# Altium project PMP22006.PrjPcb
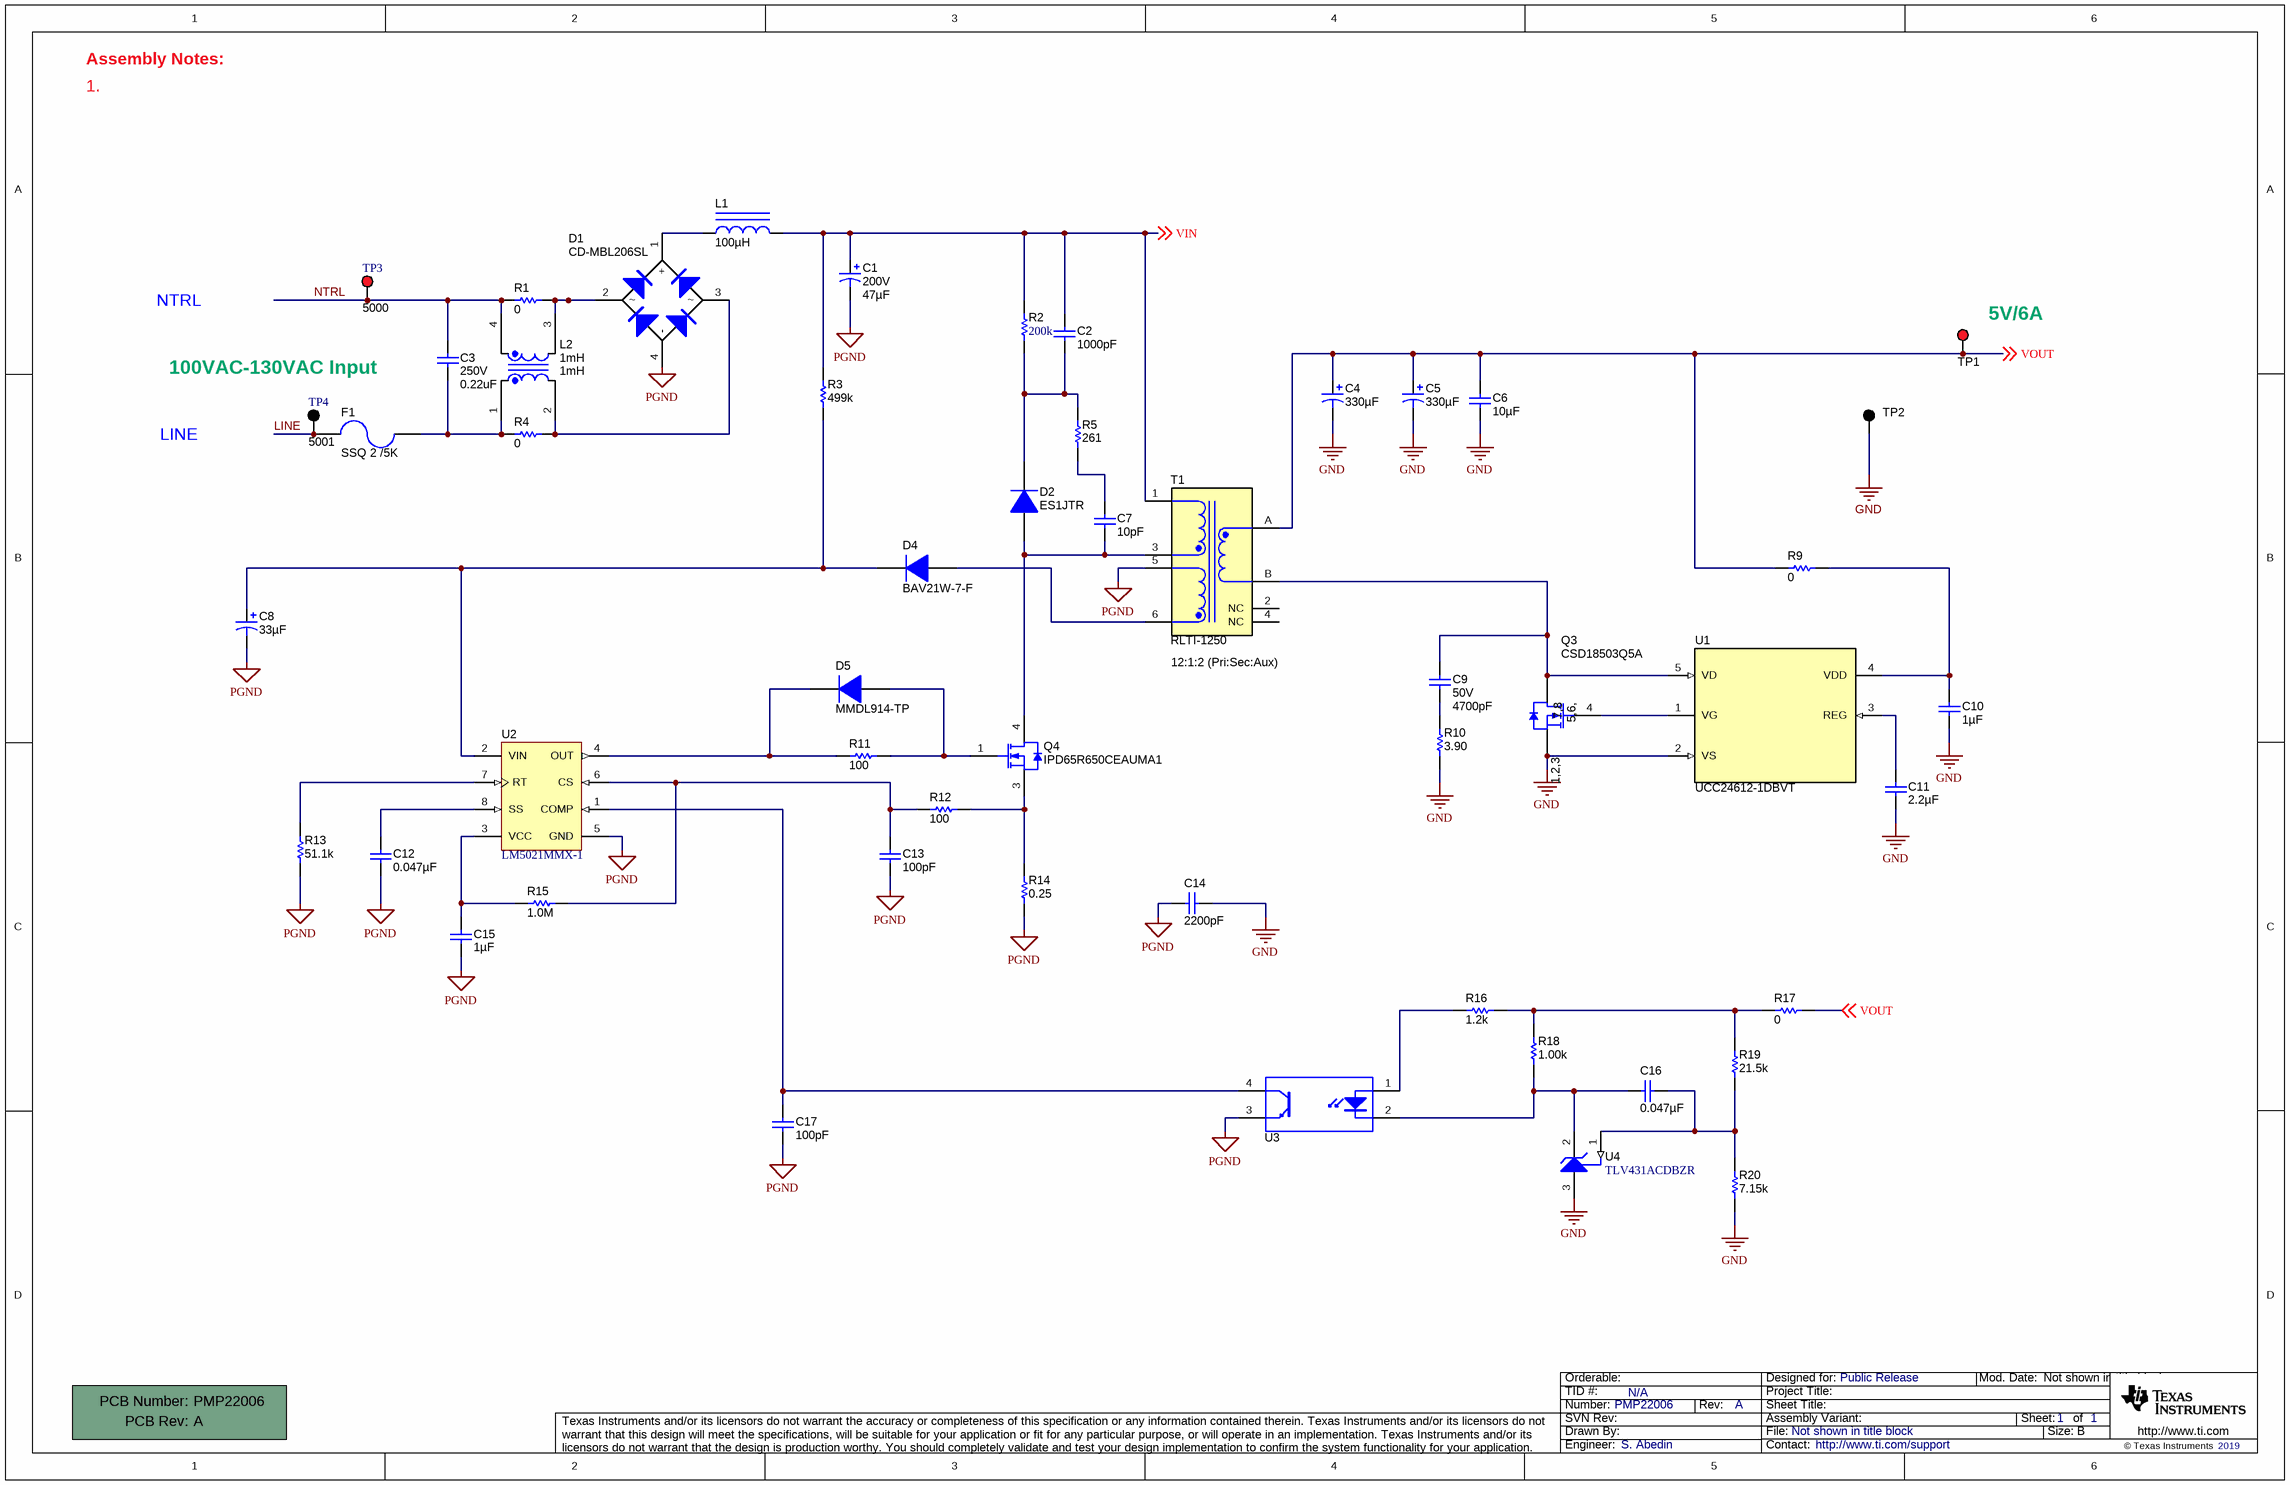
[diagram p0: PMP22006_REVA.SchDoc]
CopyrightYear: 2019; PCB_Layout: S. Abedin; PCB_Rev: A; PRJ_Customer: Public Release; PRJ_Engineer: S. Abedin; PRJ_Number: PMP22006; SCH_Rev: A; TechSupport: http://www.ti.com/support; TID: N/A
1 sheet, 53 parts. Net scope: global (net labels, ports and power ports of the same name join across sheets).
Board file: PMP22006_PCB.PcbDoc

## Sheet PMP22006_REVA.SchDoc
size 431 x 279 mm; Date: Not shown in title block; ApprovedBy: Not shown in title block; CheckedBy: Not shown in title block; Author: Not shown in title block; CompanyName: Not shown in title block; Engineer: Not shown in title block; Organization: Not shown in title block; Address1: Not shown in title block; Address2: Not shown in title block; Address3: Not shown in title block; Address4: Not shown in title block; DocumentNumber: 1; Revision: Use project parameter SCH_Rev; SheetNumber: 1; SheetTotal: 1; PageSetup: Record=PageOptions¦CenterHorizontal=True¦CenterVertical=True¦PrintScale=1.00¦XCorrection=1.00¦YCorrection=1.00¦PrintKind=0¦BorderSize=5000000¦LeftOffset=0¦BottomOffset=0¦Orientation=2¦PaperLength=1000¦PaperWidth=1000¦Scale=100¦PaperSource=15¦PrintQuality=600¦MediaType=1¦DitherType=10¦PaperKind=Letter¦PrintScaleMode=1

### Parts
!PCB1  Printed Circuit Board  (value not drawn)  (mechanical)
C1  VDC_V: 200V  ValueDisplayed: 47µF  [Nichicon_1250x2000_HorizontalUP]  (hidden comment: UCS2D470MHD)
C2  ValueDisplayed: 1000pF  [1206L]  (hidden comment: GRM31A7U2J102JW31D)
C3  VDC_V: 250V  ValueDisplayed: 0.22uF  [CAPRR500W60L780T780H1300]  (hidden comment: B32529D3224J)
C4  ValueDisplayed: 330µF  [S8_630x800]  (hidden comment: RS80J331MDNASQJT)
C5  ValueDisplayed: 330µF  [S8_630x800]  (hidden comment: RS80J331MDNASQJT)
C6  ValueDisplayed: 10µF  [0603]  (hidden comment: C1608X6S1A106M080AC)
C7  ValueDisplayed: 10pF  [1206L]  (hidden comment: VJ1206A100JXGAT5Z)
C8  ValueDisplayed: 33µF  [Rubycon_500x1100]  (hidden comment: 35YXH33MEFC5X11)
C9  VDC_V: 50V  ValueDisplayed: 4700pF  [0402]  (hidden comment: C1005X7R1H472K050BA)
C10  ValueDisplayed: 1µF  [0402L]  (hidden comment: GRM155R60J105KE19D)
C11  ValueDisplayed: 2.2µF  [0603L]  (hidden comment: GRM188R61C225KAAD)
C12  ValueDisplayed: 0.047µF  [0402L]  (hidden comment: GRM155R71E473KA88D)
C13  ValueDisplayed: 100pF  [0402L]  (hidden comment: GRM1555C1H101JA01D)
C14  ValueDisplayed: 2200pF  [CD45_900x600x1300]  (hidden comment: CD45-E2GA222M-NKA)
C15  ValueDisplayed: 1µF  [0603L]  (hidden comment: GRM188R61E105KA12D)
C16  ValueDisplayed: 0.047µF  [0402L]  (hidden comment: GRM155R71E473KA88D)
C17  ValueDisplayed: 100pF  [0402L]  (hidden comment: GRM1555C1H101JA01D)
D1  CD-MBL206SL  [CD-MBL2xxS]
D2  ES1JTR  [SMA]
D4  BAV21W-7-F  [SOD-123]
D5  MMDL914-TP  [SOD-323]
F1  SSQ 2 /5K  [6125FA]
L1  ValueDisplayed: 100µH  [SRN6045]  (hidden comment: SRN6045-101M)
L2  value 1mH  [WE-CMB_XS]  (hidden comment: 744821201)
Q3  CSD18503Q5A  [DQJ0008A]
Q4  IPD65R650CEAUMA1  [DPAK]
R1  ValueDisplayed: 0  [1206L]  (hidden comment: CRCW12060000Z0EA)
R2  ValueDisplayed: 200k  [1210L]  (hidden comment: ERJ-14NF2003U)
R3  ValueDisplayed: 499k  [1206L]  (hidden comment: CRCW1206499KFKEA)
R4  ValueDisplayed: 0  [1206L]  (hidden comment: CRCW12060000Z0EA)
R5  ValueDisplayed: 261  [2010]  (hidden comment: CRCW2010261RFKEF)
R9  ValueDisplayed: 0  [0402L]  (hidden comment: CRCW04020000Z0ED)
R10  ValueDisplayed: 3.90  [1206]  (hidden comment: ERJ-8RQF3R9V)
R11  ValueDisplayed: 100  [0402L]  (hidden comment: CRCW0402100RFKED)
R12  ValueDisplayed: 100  [0402L]  (hidden comment: CRCW0402100RFKED)
R13  ValueDisplayed: 51.1k  [0402]  (hidden comment: CRCW040251K1FKED)
R14  ValueDisplayed: 0.25  [1206L]  (hidden comment: CSR1206FKR250)
R15  ValueDisplayed: 1.0M  [0402L]  (hidden comment: CRCW04021M00JNED)
R16  ValueDisplayed: 1.2k  [0402]  (hidden comment: CRCW04021K20JNED)
R17  ValueDisplayed: 0  [0402L]  (hidden comment: CRCW04020000Z0ED)
R18  ValueDisplayed: 1.00k  [0603L]  (hidden comment: CRCW06031K00FKEA)
R19  ValueDisplayed: 21.5k  [0402L]  (hidden comment: CRCW040221K5FKED)
R20  ValueDisplayed: 7.15k  [0402]  (hidden comment: CRCW04027K15FKED)
T1  RLTI-1250  [Renco_RLTI-1250]
TP1  5000  [Keystone5000]  (value not drawn)
TP2  5001  [Keystone5001]  (value not drawn)
TP3  5000  [Keystone5000]
TP4  5001  [Keystone5001]
U1  UCC24612-1DBVT  [DBV0005A_L]
U2  LM5021MMX-1  [MUA08A_L]
U3  LTV-817A  [DIP254P762X350-4]  (value not drawn)
U4  TLV431ACDBZR  [DBZ0003A_N]

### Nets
GND: C4.2(-) C5.2(-) C6.2 C10.2 C11.2 C14.1 Q3.1(S) Q3.2(S) Q3.3(S) R10.1 R20.1 TP2.1 U1.2(VS) U4.3(ANODE)
PGND: C1.2(-) C8.2(-) C12.1 C13.1 C14.2 C15.2 C17.1 D1.4(-) R13.1 R14.2 T1.5 U2.5(GND) U3.3(E)
LINE: F1.2 TP4.1
NTRL: C3.1 L2.4 R1.1 TP3.1
VIN: C1.1(+) C2.1 L1.2 R2.2 R3.2 T1.1 ; off-sheet VIN
VOUT: C4.1(+) C5.1(+) C6.1 R9.1 R17.2 T1.A TP1.1 ; off-sheet VOUT
NetC2_2: C2.2 D2.1(K) R2.1 R5.2
NetC3_2: C3.2 F1.1 L2.1 R4.1
NetC7_1: C7.1 R5.1
NetC7_2: C7.2 D2.2(A) Q4.4(D) T1.3
NetC8_1: C8.1(+) D4.1(K) R3.1 U2.2(VIN)
NetC9_1: C9.1 Q3.5(D) Q3.6(D) Q3.7(D) Q3.8(D) Q3.9(D) T1.B U1.5(VD)
NetC9_2: C9.2 R10.2
NetC10_1: C10.1 R9.2 U1.4(VDD)
NetC11_1: C11.1 U1.3(REG)
NetC12_2: C12.2 U2.8(SS)
NetC13_2: C13.2 R12.2 R15.1 U2.6(CS)
NetC15_1: C15.1 R15.2 U2.3(VCC)
NetC16_1: C16.1 R18.2 U3.2(K) U4.2(CATHODE)
NetC16_2: C16.2 R19.1 R20.2 U4.1(REF)
NetC17_2: C17.2 U2.1(COMP) U3.4(C)
NetD1_1: D1.1(+) L1.1
NetD1_2: D1.2 L2.3 R1.2
NetD1_3: D1.3 L2.2 R4.2
NetD4_2: D4.2(A) T1.6
NetD5_1: D5.1(K) R11.2 U2.4(OUT)
NetD5_2: D5.2(A) Q4.1(G) R11.1
NetQ3_4: Q3.4(G) U1.1(VG)
NetQ4_3: Q4.3(S) R12.1 R14.1
NetR13_2: R13.2 U2.7(RT)
NetR16_1: R16.1 U3.1(A)
NetR16_2: R16.2 R17.1 R18.1 R19.2

Not connected (* = marked no-connect by the designer): T1 2(NC) 4(NC)

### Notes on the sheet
- Assembly Notes:
- 1.
- NTRL
- 100VAC-130VAC Input
- (near TP1) 5V/6A
- LINE
- (near T1) 12:1:2 (Pri:Sec:Aux)

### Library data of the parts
!PCB1 = PCB: Manufacturer: Any; PartNumber: PMP22006; SymbolCreator: a0412235
C1 = CMP-0076769-1: CAP, AL, 47 µF, 200 V, +/- 20%, TH; Manufacturer: Nichicon; IRMS_A: 9.8dA; SizeAreaWB_mm2: 210.25; SizeArea_mm2: 156.25; AEC Qualified: N; AEC Category: Q200; Value: 47uF; TaMax_C: 105°C; SizeZ_mm: 21.5; Polarized: Y; TaMin_C: -40°C; SizeY_mm: 12.5; U/M: EA; CompType: Capacitor; Cap_Case: 12.5x20mm
C2 = GRM31A7U2J102JW31D: CAP, CERM, 1000 pF, 630 V,+/- 5%, U2J, 1206; Manufacturer: MuRata; Polarized: N; CompType: Capacitor; Value: 1000pF; U/M: EA; Cap_F: 0.000000001; Tolerance_%: 5; VDC_V: 630; Value2: 630V; TaMin_C: -55; TaMax_C: 125; Cap_Case: 1206; SizeArea_mm2: 5.12; SizeAreaWB_mm2: 10.92; SizeX_mm: 3.2; SizeY_mm: 1.6; SizeZ_mm: 1.35; AEC Category: Q200
C3 = CMP-0012341-1: CAP, Film, 0.22 uF, 250 V, +/- 5%, TH; Manufacturer: TDK; TaMin_C: -55°C; Polarized: N; SizeAreaWB_mm2: 96.04; Value1: Unknown; U/M: EA; Value: 0.22uF; TaMax_C: 125°C; SizeZ_mm: 13; SizeX_mm: 7.8; Cap_Case: 7.8x13x7.8; SizeArea_mm2: 60.84; Cap_F: 220nF; AEC Category: Q200
C4 C5 = RS80J331MDNASQJT: CAP, Aluminum Polymer, 330 µF, 6.3 V,+/- 20%, 0.008 ohm, TH; Manufacturer: Nichicon; Polarized: Y; CompType: Capacitor; Value: 330uF; U/M: EA; Cap_F: 0.00033; Tolerance_%: 20; VDC_V: 6.3; Value2: 6.3V; ESR_ohm: 0.008; IRMS_A: 5; TaMin_C: -55; TaMax_C: 105; Cap_Case: 6.3X8mm; SizeAreaWB_mm2: 68.89; SizeArea_mm2: 39.69; SizeZ_mm: 9; AEC Category: Q200; AEC Qualified: N
C6 = C1608X6S1A106M080AC: CAP, CERM, 10 µF, 10 V,+/- 10%, X6S, 0603; Manufacturer: TDK; Polarized: N; CompType: Capacitor; Value: 10uF; U/M: EA; Cap_F: 0.00001; Tolerance_%: 10; ESR_ohm: 0.004639; Value1: 0.004639 ohm; Value2: 10V; IRMS_A: 2.41407; TaMin_C: -55; TaMax_C: 105; SizeArea_mm2: 1.28; SizeAreaWB_mm2: 4.68; SizeX_mm: 1.6; SizeY_mm: 0.8; SizeZ_mm: 1; AEC Category: Q200
C7 = VJ1206A100JXGAT5Z: CAP, CERM, 10 pF, 1000 V,+/- 5%, C0G/NP0, 1206; Manufacturer: Vishay-Vitramon; Polarized: N; CompType: Capacitor; Value: 10pF; U/M: EA; Cap_F: 0.00000000001; Tolerance_%: 5; VDC_V: 1000; Value2: 1000V; TaMin_C: -55; TaMax_C: 125; Cap_Case: 1206; SizeArea_mm2: 5.12; SizeAreaWB_mm2: 10.92; SizeX_mm: 3.2; SizeY_mm: 1.6; SizeZ_mm: 1.35; AEC Category: Q200
C8 = 35YXH33MEFC5X11: CAP, AL, 33 µF, 35 V, +/- 20%, TH; Manufacturer: Rubycon; Polarized: Y; CompType: Capacitor; Value: 33uF; U/M: EA; Cap_F: 0.000033; Tolerance_%: 20; Value1: Unknown; VDC_V: 35; Value2: 35V; IRMS_A: 0.21; TaMin_C: -40; TaMax_C: 105; Cap_Case: 5x11mm; SizeAreaWB_mm2: 49; SizeArea_mm2: 25; SizeX_mm: 5; SizeZ_mm: 12.5; AEC Category: Q200; AEC Qualified: N
C9 = CMP-0078221-1: CAP, CERM, 4700 pF, 50 V,+/- 10%, X7R, 0402; Manufacturer: TDK; TaMin_C: -55°C; Polarized: N; SizeAreaWB_mm2: 3; U/M: EA; Value: 4700pF; TaMax_C: 125°C; SizeZ_mm: 0.6; SizeX_mm: 1; SizeY_mm: 0.5; Cap_F: 4.7nF; AEC Category: Q200
C10 = GRM155R60J105KE19D: CAP, CERM, 1 µF, 6.3 V, +/- 10%, X5R, 0402; Manufacturer: MuRata; Polarized: N; CompType: Capacitor; Value: 1uF; U/M: EA; Cap_F: 0.000001; Tolerance_%: 10; Value1: Unknown; VDC_V: 6.3; Value2: 6.3V; TaMin_C: -55; TaMax_C: 85; Cap_Case: 0402; SizeArea_mm2: 0.5; SizeAreaWB_mm2: 3; SizeX_mm: 1; SizeZ_mm: 0.6; AEC Category: Q200
C11 = GRM188R61C225KAAD: CAP, CERM, 2.2 µF, 16 V,+/- 10%, X5R, 0603; Manufacturer: MuRata; Polarized: N; CompType: Capacitor; Value: 2.2uF; U/M: EA; Cap_F: 0.0000022; Tolerance_%: 10; Value1: Unknown; VDC_V: 16; Value2: 16V; TaMin_C: -55; TaMax_C: 85; Cap_Case: 0603; SizeArea_mm2: 1.28; SizeAreaWB_mm2: 4.68; SizeX_mm: 1.6; SizeY_mm: 0.8; SizeZ_mm: 1; AEC Category: Q200; Green_Lifecycle: Not Set; Green_REACh: Incomplete
C12 C16 = GRM155R71E473KA88D: CAP, CERM, 0.047 µF, 25 V, +/- 10%, X7R, 0402; Manufacturer: MuRata; Polarized: N; CompType: Capacitor; Value: 0.047uF; U/M: EA; Cap_F: 0.000000047; Tolerance_%: 10; Value1: Unknown; VDC_V: 25; Value2: 25V; TaMin_C: -55; TaMax_C: 125; Cap_Case: 0402; SizeArea_mm2: 0.5; SizeAreaWB_mm2: 3; SizeX_mm: 1; SizeZ_mm: 0.6; AEC Category: Q200
C13 C17 = GRM1555C1H101JA01D: CAP, CERM, 100 pF, 50 V,+/- 5%, C0G/NP0, 0402; Manufacturer: MuRata; Polarized: N; CompType: Capacitor; Value: 100pF; U/M: EA; Cap_F: 0.0000000001; Tolerance_%: 5; Value1: Unknown; VDC_V: 50; Value2: 50V; TaMin_C: -55; TaMax_C: 125; Cap_Case: 0402; SizeArea_mm2: 0.5; SizeAreaWB_mm2: 3; SizeX_mm: 1; SizeZ_mm: 0.6; AEC Category: Q200; Green_Lifecycle: Active; Green_REACh: Passed
C14 = CD45-E2GA222M-NKA: CAP, CERM, 2200 pF,  V, +/- 20%, E, D9xT6mm; Manufacturer: TDK; Value: 2200pF; Polarized: N; CompType: Capacitor; U/M: EA; Cap_F: 0.0000000022; Tolerance_%: 20; Value1: Unknown; TaMin_C: -25; TaMax_C: 125; Cap_Case: 9x6x13mm; SizeArea_mm2: 63.9; SizeAreaWB_mm2: 101.2; SizeX_mm: 10.65; SizeY_mm: 6; SizeZ_mm: 13; AEC Category: Q200
C15 = GRM188R61E105KA12D: CAP, CERM, 1 µF, 25 V, +/- 10%, X5R, 0603; Manufacturer: MuRata; Polarized: N; CompType: Capacitor; Value: 1uF; U/M: EA; Cap_F: 0.000001; Tolerance_%: 10; Value1: Unknown; VDC_V: 25; Value2: 25V; TaMin_C: -55; TaMax_C: 85; Cap_Case: 0603; SizeArea_mm2: 1.28; SizeAreaWB_mm2: 4.68; SizeX_mm: 1.6; SizeY_mm: 0.8; SizeZ_mm: 1; AEC Category: Q200
D1 = CD-MBL206SL: Diode, P-N-Bridge, 600 V, 2 A, 5.8x5.3mm; Manufacturer: Bourns; U/M: EA; Vf_V: 0.96; Value: 600V; Value1: 2A; Value2: 0.96V; Io_A: 2; Vr_V: 600; TJmax_C: 175; RJC_CperW: 15; SizeAreaWB_mm2: 47.092; SizeArea_mm2: 23.452; SizeX_mm: 5.72; SizeY_mm: 4.1; SizeZ_mm: 1.35; AEC Category: Q101; AEC Qualified: N
D2 = ES1JTR: Diode, Superfast Rectifier, 600 V, 1 A, SMA; Manufacturer: SMC Diode Solutions; U/M: EA; Vf_V: 1.7; Value: 600V; Value1: 1A; Value2: 1.7V; Io_A: 1; Vr_V: 600; TJmax_C: 150; RJC_CperW: 35; SizeAreaWB_mm2: 37.3428; SizeArea_mm2: 16.3228; SizeX_mm: 5.59; SizeY_mm: 2.92; SizeZ_mm: 2.87; AEC Category: Q101; AEC Qualified: N
D4 = BAV21W-7-F: Diode, Switching, 200 V, 0.2 A, SOD-123; Manufacturer: Diodes Inc.; U/M: EA; Vf_V: 1.25; Value: 200V; Value1: 0.2A; Value2: 1.25V; Io_A: 0.2; Vr_V: 200; TJmax_C: 150; SizeAreaWB_mm2: 13.095; SizeArea_mm2: 6.545; SizeX_mm: 3.85; SizeY_mm: 1.7; SizeZ_mm: 1.35; AEC Category: Q101; Green_Lifecycle: Active; Green_REACh: Passed
D5 = MMDL914-TP: Diode, Switching, 100 V, 0.2 A, SOD-323; Manufacturer: Micro Commercial Components; U/M: EA; Vf_V: 1; Value: 100V; Value1: 0.2A; Value2: 1V; Io_A: 0.2; Vr_V: 100; TJmax_C: 150; SizeAreaWB_mm2: 8.695; SizeArea_mm2: 3.645; SizeX_mm: 2.7; SizeY_mm: 1.35; AEC Category: Q101
F1 = 6125FA2A: Fuse, 2 A, 125VAC/VDC, SMD; Manufacturer: Bel Fuse Inc.; VDC_V: 125; Interrupt_DC: 300; Interrupt_AC: 50; Irating_A: 2; Rtyp_Ohm: 0.05; MeltingTyp: 0.8
L1 = SRN6045-680M: FIXED IND 100UH 700MA 494 MOHM; Manufacturer: Bourns; CompType: Inductor; Ind_H: 68.0E-6; Imax_A: 0.9; Irms: 0.9A @ 40C rise; Isat: 1A @ 30% inductance drop; DCR_ohm: 0.351; Value1: 0.351 ohm; Value2: 0.9A; Material: Ferrite; SizeAreaWB_mm2: 64; SizeArea_mm2: 36; SizeX_mm: 6; SizeZ_mm: 4.5; AEC Category: Q200
L2 = CMP-0013113-1: Coupled inductor, 1 mH, 2 A, 0.045 ohm, TH; Manufacturer: Wurth Elektronik; SizeAreaWB_mm2: 161.5; DCR_ohm: 0.045; SizeZ_mm: 20.5; SizeX_mm: 15; SizeY_mm: 7.5; SizeArea_mm2: 112.5
Q3 = CSD18503Q5A: MOSFET, N-CH, 40 V, 100 A, DQJ0008A (VSONP-8); Manufacturer: Texas Instruments; Alternate Manufacturer: None; U/M: EA; ChType: N; Value: 40V; VdsMax_V: 40; Value1: 0.0062 ohm; Rdson45_ohm: 0.0062; Value2: 13 nC; QgTyp_nC: 13; Vgs_V: 20; IdsMax_A: 100; SizeAreaWB_mm2: 55.2; SizeArea_mm2: 29.4; SizeX_mm: 6; SizeY_mm: 4.9; SizeZ_mm: 1.1; AEC Category: Q101
Q4 = IPD65R650CEAUMA1: MOSFET, N-CH, 650 V, 10.1 A, DPAK; Manufacturer: Infineon Technologies; Alternate Manufacturer: None; U/M: EA; ChType: N; Value: 650V; VdsMax_V: 650; Value1: ? ohm; Value2: 23 nC; QgTyp_nC: 23; Vgs_V: 20; IdsMax_A: 10.1; SizeAreaWB_mm2: 101.7114; SizeArea_mm2: 64.8114; SizeX_mm: 9.91; SizeY_mm: 6.54; SizeZ_mm: 2.29; AEC Category: Q101
R1 R4 = CRCW12060000Z0EA: RES, 0, 5%, 0.25 W, 1206; Manufacturer: Vishay-Dale; CompType: Resistor; Value: 0; Value_Code: 0000; Tolerance_%: 5; Power_W: 0.25; Value2: 0.25W; VDC_V: 200; TempCo: 200 ppm/C; EIA_Code: E24; U/M: EA; AEC Category: Q200
R2 = ERJ-14NF2003U: RES, 200 k, 1%, 0.5 W, 1210; Manufacturer: Panasonic; CompType: Resistor; Value: 200k; Res_ohm: 200000; Tolerance_%: 1; Power_W: 0.5; Value2: 0.5W; VDC_V: 200; TempCo: 100 ppm/C; SizeArea_mm2: 8; SizeAreaWB_mm2: 14.7; SizeX_mm: 3.2; SizeY_mm: 2.5; SizeZ_mm: 1.35; EIA_Code: E96; U/M: EA; AEC Category: Q200
R3 = CRCW1206499KFKEA: RES, 499 k, 1%, 0.25 W, 1206; Manufacturer: Vishay-Dale; CompType: Resistor; Value: 499k; Res_ohm: 499000; Tolerance_%: 1; Power_W: 0.25; Value2: 0.25W; VDC_V: 200; TempCo: 100 ppm/C; SizeArea_mm2: 5.12; SizeX_mm: 3.2; SizeY_mm: 1.6; SizeZ_mm: 1.35; EIA_Code: E96; U/M: EA; AEC Category: Q200; Green_Lifecycle: Active; Green_REACh: Passed
R5 = CMP-0016331-2: RES, 261, 1%, 0.75 W, AEC-Q200 Grade 0, 2010; Manufacturer: Vishay-Dale; Power_W: 750mW; TempCo: 100 ppm/C; Value_Code: 261R; U/M: EA; Value: 261; EIA_Code: E96; SizeX_mm: 5; SizeY_mm: 2.5; SizeZ_mm: 1.66; Value2: 0.75W; SizeArea_mm2: 12.5; AEC Qualified: Y; VDC_V: 400V; AEC Grade: 0; AEC Category: Q200
R9 R17 = CRCW04020000Z0ED: RES, 0, 5%, 0.063 W, 0402; Manufacturer: Vishay-Dale; CompType: Resistor; Value: 0; Value_Code: 0000; Tolerance_%: 5; Power_W: 0.063; Value2: 0.063W; VDC_V: 50; TempCo: 200 ppm/C; EIA_Code: E24; U/M: EA
R10 = CMP-0017780-1: RES, 3.90, 1%, 0.25 W, 1206; Manufacturer: Panasonic; Power_W: 250mW; TempCo: 200 ppm/C; Value_Code: 3R90; U/M: EA; Value: 3.90; Res_ohm: 3.9; SizeX_mm: 3.2; SizeY_mm: 1.6; SizeZ_mm: 1.35; Value2: 0.25W; SizeArea_mm2: 5.12; AEC Category: Q200
R11 R12 = CRCW0402100RFKED: RES, 100, 1%, 0.063 W, 0402; Manufacturer: Vishay-Dale; CompType: Resistor; Value: 100; Value_Code: 100R; Tolerance_%: 1; Power_W: 0.063; Value2: 0.063W; VDC_V: 50; TempCo: 100 ppm/C; EIA_Code: E96; U/M: EA; AEC Category: Q200; SizeArea_mm2: 0.5; SizeZ_mm: 0.6
R13 = CRCW040251K1FKED: RES, 51.1 k, 1%, 0.063 W, 0402; Manufacturer: Vishay-Dale; CompType: Resistor; Value: 51.1k; Res_ohm: 51100; Value_Code: 51k1; Tolerance_%: 1; Power_W: 0.063; Value2: 0.063W; VDC_V: 50; TempCo: 100 ppm/C; SizeArea_mm2: 0.5; SizeZ_mm: 0.6; EIA_Code: E96; U/M: EA; AEC Category: Q200; Green_Lifecycle: Active; Green_REACh: Passed
R14 = CSR1206FKR250: RES, 0.25, 1%, 0.5 W, 1206; Manufacturer: Stackpole Electronics Inc; CompType: Resistor; Value: 0.25; Value_Code: R250; Tolerance_%: 1; Power_W: 0.5; Value2: 0.5W; TempCo: 100 ppm/C; U/M: EA; AEC Category: Q200; SizeArea_mm2: 5.12; SizeX_mm: 3.2; SizeY_mm: 1.6; SizeZ_mm: 1.35
R15 = CRCW04021M00JNED: RES, 1.0 M, 5%, 0.063 W, 0402; Manufacturer: Vishay-Dale; CompType: Resistor; Value: 1.0Meg; Res_ohm: 1000000; Value_Code: 1M00; Tolerance_%: 5; Power_W: 0.063; Value2: 0.063W; VDC_V: 50; TempCo: 200 ppm/C; EIA_Code: E24; U/M: EA; AEC Category: Q200; SizeArea_mm2: 0.5; SizeX_mm: 1; SizeZ_mm: 0.6
R16 = CRCW04021K20JNED: RES, 1.2 k, 5%, 0.063 W, 0402; Manufacturer: Vishay-Dale; CompType: Resistor; Value: 1.2k; Res_ohm: 1200; Value_Code: 1k20; Tolerance_%: 5; Power_W: 0.063; Value2: 0.063W; VDC_V: 50; TempCo: 200 ppm/C; SizeArea_mm2: 0.5; SizeX_mm: 1; SizeZ_mm: 0.6; EIA_Code: E24; U/M: EA; AEC Category: Q200; Green_Lifecycle: Active; Green_REACh: Passed
R18 = CRCW06031K00FKEA: RES, 1.00 k, 1%, 0.1 W, 0603; Manufacturer: Vishay-Dale; CompType: Resistor; Value: 1.00k; Res_ohm: 1000; Value_Code: 1k00; Tolerance_%: 1; Power_W: 0.1; Value2: 0.1W; VDC_V: 75; TempCo: 100 ppm/C; EIA_Code: E96; U/M: EA; AEC Category: Q200
R19 = CRCW040221K5FKED: RES, 21.5 k, 1%, 0.063 W, 0402; Manufacturer: Vishay-Dale; CompType: Resistor; Value: 21.5k; Res_ohm: 21500; Value_Code: 21k5; Tolerance_%: 1; Power_W: 0.063; Value2: 0.063W; VDC_V: 50; TempCo: 100 ppm/C; EIA_Code: E96; U/M: EA; AEC Category: Q200; SizeArea_mm2: 0.5; SizeZ_mm: 0.6
R20 = CRCW04027K15FKED: RES, 7.15 k, 1%, 0.063 W, 0402; Manufacturer: Vishay-Dale; CompType: Resistor; Value: 7.15k; Res_ohm: 7150; Value_Code: 7k15; Tolerance_%: 1; Power_W: 0.063; Value2: 0.063W; VDC_V: 50; TempCo: 100 ppm/C; SizeArea_mm2: 0.5; SizeZ_mm: 0.6; EIA_Code: E96; U/M: EA; AEC Category: Q200; Green_Lifecycle: Active; Green_REACh: Passed
T1 = CMP-0076771-1: Transformer, 400 uH, TH / OLD build serial NUmber: S52882 / NEW: S56188; Manufacturer: Renco Electronics; SizeAreaWB_mm2: 756.6772; SizeArea_mm2: 649.6812; AEC Qualified: N; Lp: 400.0; AEC Category: Q200; Value: 400uH; SizeZ_mm: 13.716; Ind_H: 400µH; SizeY_mm: 22.098; LeakageInd_H: 7µH; Rsec1_ohm: 4m; DCR_ohm: 5d; SizeX_mm: 29.4
TP1 = 5000: Test Point, Miniature, Red, TH; Manufacturer: Keystone; CompType: Test Point Loop; ContactFinish: Silver; Green_Lifecycle: Active; Green_REACh: Passed
TP2 = 5001: Test Point, Miniature, Black, TH; Manufacturer: Keystone; CompType: Test Point Loop; ContactFinish: Silver; Green_Lifecycle: Active; Green_REACh: Passed
TP3 = CMP-0055137-1: Test Point, Miniature, Red, TH; Manufacturer: Keystone; CNHeader: FALSE; Green_Lifecycle: Active; Green_REACh: Passed; ContactFinish: Silver; CT: TRUE
TP4 = CMP-0055138-1: Test Point, Miniature, Black, TH; Manufacturer: Keystone; CNHeader: FALSE; Green_Lifecycle: Active; Green_REACh: Passed; ContactFinish: Silver; CT: TRUE
U1 = UCC24612-2DBVT: UCC24612-1DBV, DBV0005A (SOT-23-5); Manufacturer: Texas Instruments; SymbolCreator: Altium; SizeArea_mm2: 8.12; SizeAreaWB_mm2: 14.82; SizeX_mm: 2.8; SizeY_mm: 2.9; SizeZ_mm: 1.45; CompType: IC; U/M: EA
U2 = LM5021MMX-1: AC-DC Current Mode PWM Controller, 8-pin MSOP; Manufacturer: Texas Instruments; PackageTopMarking: ZXTT*21-1; PowerWise: N; CompType: Switcher
U3 = LTV-817S: Optocoupler, 5 kV, 50-600% CTR, SMT; Manufacturer: Lite-On; CTR (Min): 50%; CTR (Max): 600%; Voltage_Isolation_Vrms: 5000V; SizeAreaWB_mm2: 80.256; SizeArea_mm2: 46.736; SizeX_mm: 10.16; SizeY_mm: 4.6
U4 = TLV431ACDBZR: Low Voltage Adjustable Precision Shunt Regulator, 39 ppm / degC, 15 mA, 0 to 70 degC, 3-pin SOT-23 (DBZ), Green (RoHS & no Sb/Br); Manufacturer: Texas Instruments; Alternate PartNumber: Equivalent; Iout/Iz(Max)(mA): 15; Min Iz for Regulation(uA): 80; Rating: Catalog; SubFamily: Shunt Voltage Reference; Temp Coeff(Max)(ppm/ degree C): 129; Temp Coeff(Typ)(ppm/ degree C): 39; VO Adj(Max)(V): 6; VO Adj(Min)(V): 1.24

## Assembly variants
001: not fitted R1 R4 R15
